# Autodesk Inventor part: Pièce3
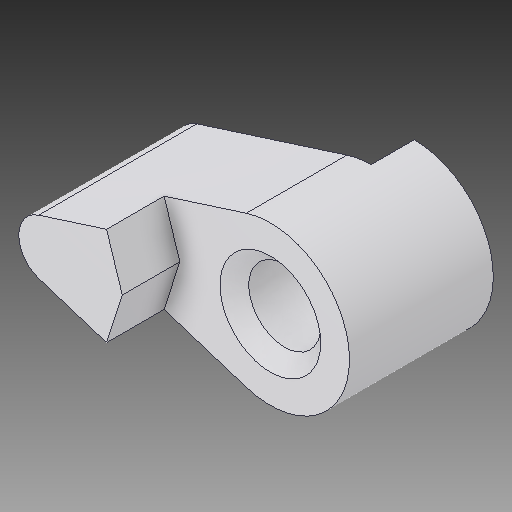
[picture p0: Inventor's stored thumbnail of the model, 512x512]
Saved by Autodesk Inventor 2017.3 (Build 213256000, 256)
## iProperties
Created: 2007-11
Part Number: Pièce3
Material: solidworks materials|Alliage 7079|22
Document SubType Name: Modeling
Designer: ficho
Density: 2.7 g/cm^3
Appearance: 227,227,233
Author: ficho
Sending System: SolidWorks 2009
Last Author: christophe
Last Saved: 2011-01-17
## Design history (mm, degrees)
feature "Chanfrein1"
node "Solide1"
